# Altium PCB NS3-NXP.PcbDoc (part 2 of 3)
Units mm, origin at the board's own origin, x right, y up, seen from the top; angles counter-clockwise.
Board outline 147 x 83 mm, 2 copper layers (Top Layer, Bottom Layer); 303 components, 312 nets, 1163 pads, 118 vias.
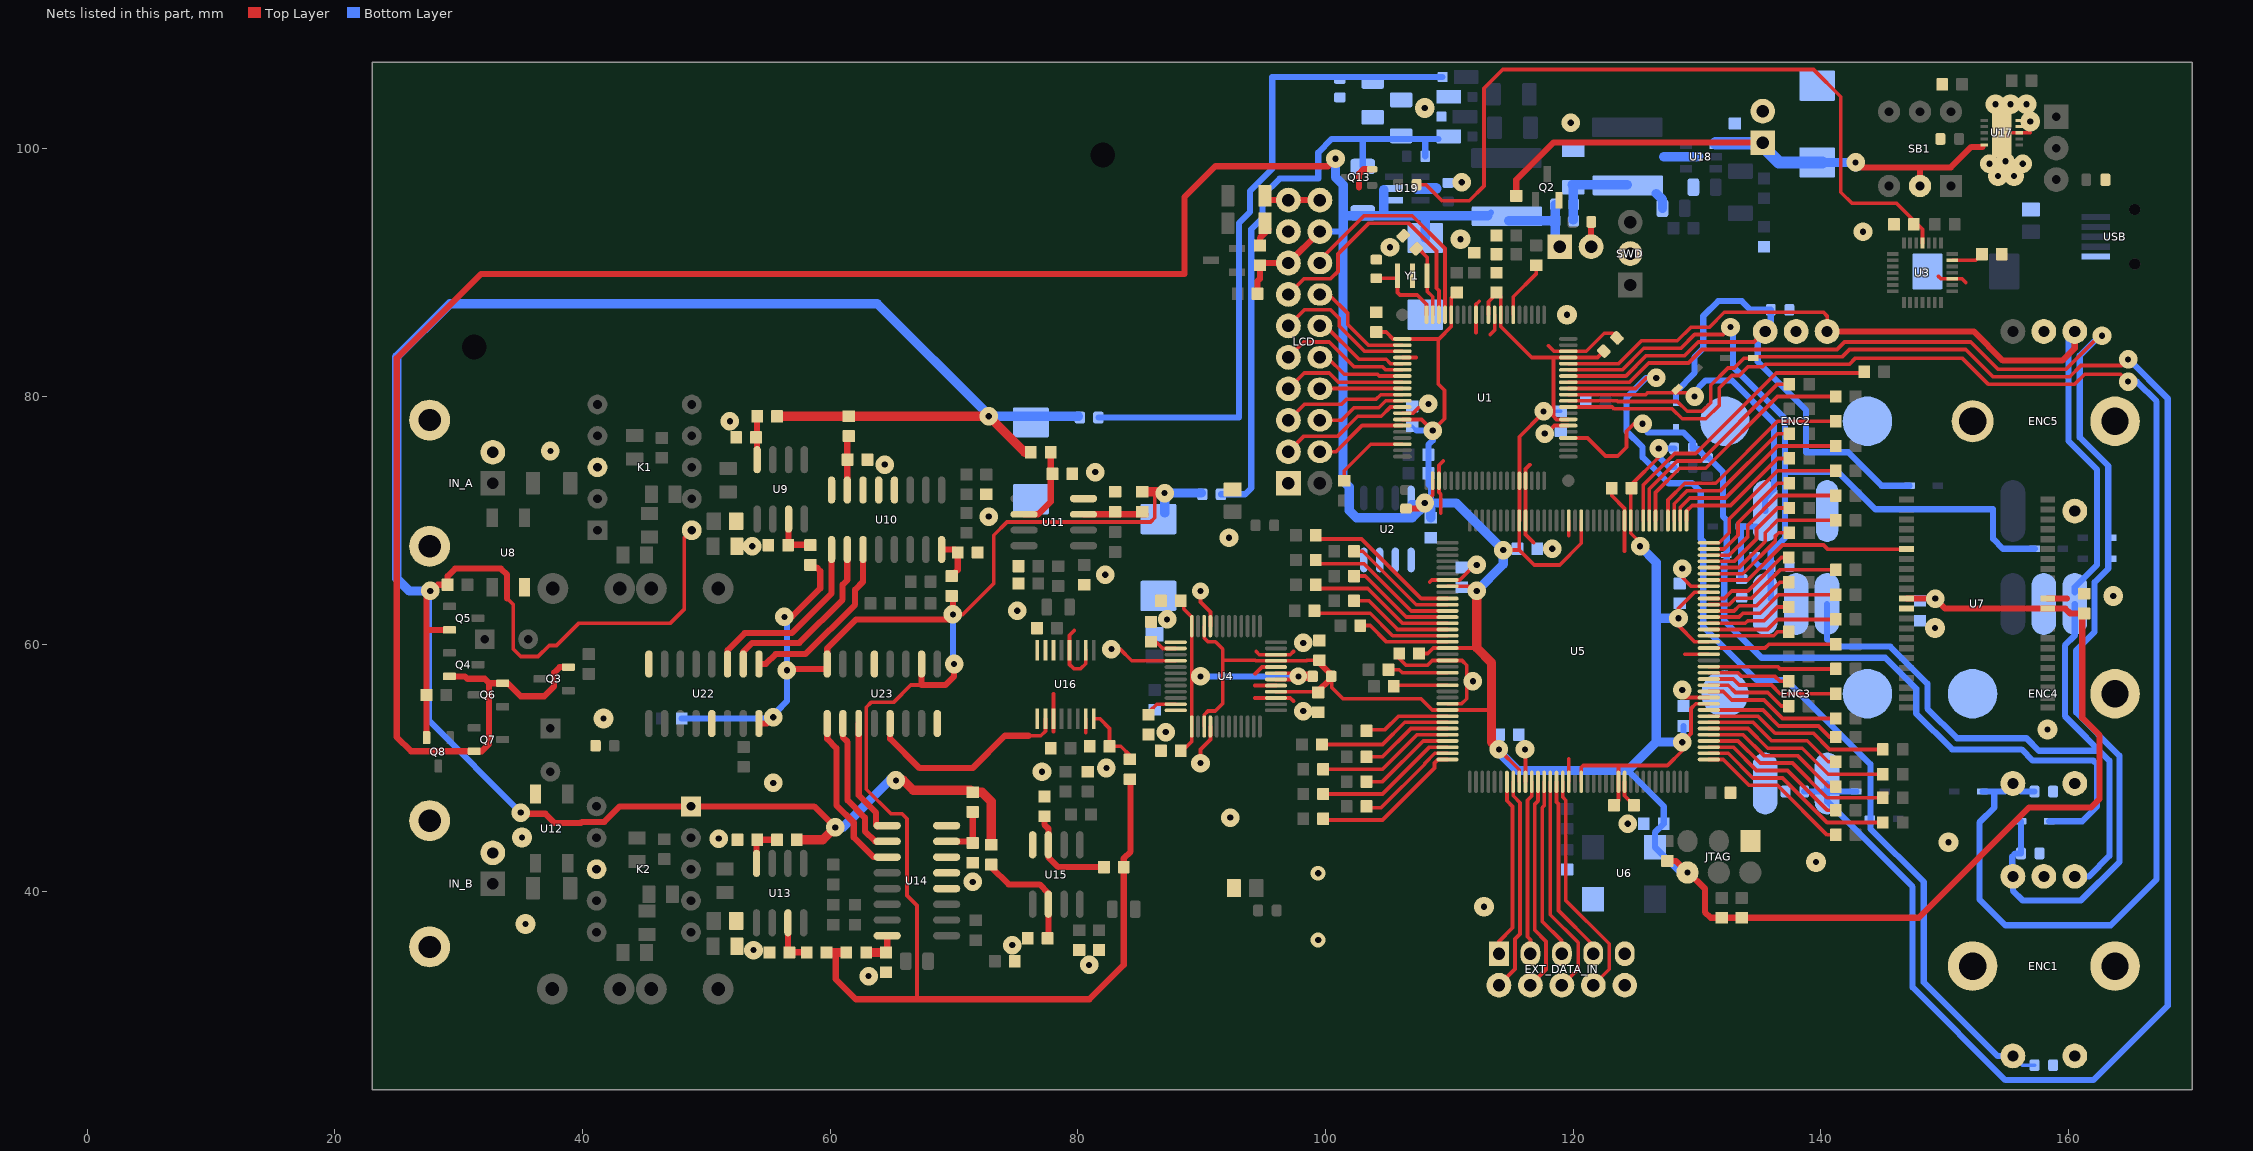
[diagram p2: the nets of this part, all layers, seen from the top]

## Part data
B1 B2 B3 B4 B5 B6 B7 B8 B9 B10 B11 B12 B13 B14: library part BLM18PG181SN1D, "Bead 0603 size for power lines"
B15 B16 B17 B18: library part BLM18AG601SN1D, "0603 size for general signal lines"
BATERY BOOZ: "Header, 2-Pin"
C1 C2 C3 C4 C5 C6 C9 C12 C13 C14 C16 C17 C18 C19 C20 C21 C23 C24 C25 C26 C28 C29 C30 C32 C33 C34 C45 C46 C47 C48 C51 C52 C60 C61 C62 C63 C66 C67 C70 C83 C84: library part CL10B104KB8NNNC
C7 C8: library part CL10C220JB8NNNC
C10 C49 C64: library part GRM188R61C225KE15D
C11 C81: library part 293D476X9010D2T
C15 C50 C65 C80: library part GRM21BR61A106KE19L
C40 C55: library part GRM31C5C1H104JA01L
C41 C43 C56 C58: "Variable or Adjustable Capacitor"
C42 C57: library part CL21C222JBFNNNE
C44 C53 C59 C68: library part C0603C151J5GAC7867
C54 C69: "Aluminium Electrolitic Capacitor"
C71: library part GRM188R61C225KE15D, "General Purpose"
C86 C88 C89 C90 C92: library part GRM31CR71H475KA12L
C87 C91 C93: library part TR3D107K016C0150
C110 C111 C112 C113 C114 C115 C116 C117: library part CL10C102JB8NNNC
D1: library part D_C_LightDiode_3pin_OA
D2 D22: library part LL4151-GS8, "Small Signal Fast Switching Diode"
D5 D6 D7 D8 D9 D10 D11 D12 D13 D14 D15 D16 D17: library part PMEG2020EJ,115, "20V, 2A very low VF MEGA Schottky barrier rectifiers"
D18 D19 D20 D21: library part MSS1P3L-M3/89A, "30V, 1A, eSMP, Surface Mount Schottky Barrier Rectifiers"
ENC1 ENC2 ENC3 ENC4 ENC5: "Rotary Encoder with button"
EXT_DATA_IN: library part BH-10_2
IN_A IN_B: "BNC Elbow Connector"
JTAG: "Header, 3-Pin, Dual row"
K1 K2: library part A–5W–K, "5V переключающее реле."
L1 L2: library part NR6028T220M, "Shielded Power Inductor Wire Wound H=2.8mm"
LCD: "Header, 10-Pin, Dual row"
Q1: "NPN General-purpose Transistor"
Q2 Q5 Q8: library part IRLML2402TRPBF, "20V, 0.25 Ohm, Single N-Channel HEXFET Power MOSFET"
Q3 Q4 Q6 Q7: library part IRLML6302TRPBF, "20V, 0.7A Single P-Channel HEXFET Power MOSFET"
Q13: library part MMBT3904WT1G, "40 V, 200 mA NPN general-purpose transistors"
R1 R2 R9 R10 R12 R18 R19 R107 R108 R128 R136 R137 R150 R151 Rt: library part 0603SAF1002T50
R3 R8: library part CRCW12062R00FKEA
R6 R105 R125: library part TC0350F1002T5E, "TC03 (0603) 1/16W 1% 10.0K 50PPM T/R-5000"
R7: library part TC0350F5101T5E, "TC03 (0603) 1/16W 1% 5.1K 50PPM T/R-5000"
R14 R129: library part ERJ3EKF1001V
R15 R97 R117: library part 0603SAF1000T50
R20 R21 R22 R23 R24 R25 R26 R27 R28 R29 R30 R31 R32 R33 R34 R35 R36 R37 R38 R39 R40 R41 R42 R43 R44 R45 R46 R47 R48 R49 R50 R51 R52 R53 R54 R55 R56 R57 R58 R59 R60 R61 R62 R63 R64 R65 R66 R67 R68 R69 R70 R71 R72 R73 R74 R75 R76 R77 R78 R79 R80 R99 R100 R119 R120: library part 0603SAF330JT50
R88 R109 R130 R135: library part ERA3AED102V
R89 R90 R91 R110 R111 R112 R127: library part 0805S8F5100T50
R92 R93 R113: library part 0805S8F1002T50
R94 R114: library part 0805S8F1001T50
R95 R115: library part TC0350F4990T5E, "TC03 (0603) 1/16W 1% 499E 50PPM T/R-5000"
R96 R101 R116 R121: library part 0603SAF3300T50
R98: library part RR0816P-4992-D-68C
R102 R103 R122 R123: library part 0603SAF2701T50
R104 R124: library part RC0805FR-0710KL, "General Purpose Chip Resistor"
R106 R126: library part TC0310C3001T5E, "TC03 (0603) 1/16W 0.25% 3.00K 10PPM T/R-5000"
R118: library part 0805S8F4700T50
R131: library part 0603SAF2001T50
R132: library part 0603SAF1503T50
R133 R138: library part 0603SAF1003T50
R141 R142: library part 0805S8F1502T50
R143 R144 R145: library part 0603SAF2201T50
SWD: "Header, 3-Pin"
U1: library part LPC1758FBD80,551, "32-bit ARM Cortex-M3 MCU, 512kB flash 32kB SRAM with Ethernet, USB 2.0 Host/Device/OTG, CAN"
U2: library part M24C64MN1, "64 Kbit Serial IІC Bus EEPROM"
U3: "USB-RS232 Converter"
U4: "2 x 8bit 100MSPS ADC converter"
U5: library part QFP-144, "PQFP-144/TQFP-144"
U6: library part KXO-V97, "Clock Oscillator"
U7: "SRAM"
U8 U12: "Opto Switch"
U10 U14: library part MC74HC4051AD, "Analog Multiplexer/Demultiplexer"
U17: "Li-Ion Battery Charger"
U18: "DC-DC Step-Down converter"
U19: library part MT3608, "2A Step Up Converter"
U22 U23: library part M74HC595M1R, "8 Bit Shift Register with Output Latches (3 STATE)"
USB: library part "USB MINIB"
Y1: library part CSTCE10M0G55Z-R0, "SMD 10 MHz 0.5%, 0.2%(TC) Build in Load Capacitance 33pF ± 20%"

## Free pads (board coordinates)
  round 1.524 hole 2: 0(31.25,84) 0(82,99.5)

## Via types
v1: diameter 1.5, hole 0.5, Top Layer to Bottom Layer, 93 vias
v2: diameter 1.6, hole 0.5, Top Layer to Bottom Layer, 18 vias
v3: diameter 1.4, hole 0.5, Top Layer to Bottom Layer, 4 vias
v4: diameter 1.2, hole 0.5, Top Layer to Bottom Layer, 2 vias
v5: diameter 1.3, hole 0.5, Top Layer to Bottom Layer, 1 vias

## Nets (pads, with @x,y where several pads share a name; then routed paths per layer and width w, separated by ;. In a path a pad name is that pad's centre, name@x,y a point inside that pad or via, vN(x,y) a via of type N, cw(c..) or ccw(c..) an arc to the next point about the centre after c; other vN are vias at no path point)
0A: U10.11 U22.1 | length 14.5
  Top Layer w0.5: U22.1@54.245,58.4 54.8,58.4 55.6,59.2 58,59.2 62,63.2 62,64.4 62.645,65.045 U10.11@62.645,67.65
0B: U14.11 U23.1 | length 13.4
  Top Layer w0.5: U23.1@59.755,53.6 59.755,52.345 60.5,51.6 60.5,47 61.9,45.6 61.9,44.4 63.495,42.805 U14.11@64.6,42.805
1A: U10.10 U22.2 | length 15
  Top Layer w0.5: U22.2@52.975,58.4 52.975,59.375 53.7,60.1 57.5,60.1 61,63.6 61,64.8 61.375,65.175 U10.10@61.375,67.65
1B: U14.10 U23.2 | length 11.6
  Top Layer w0.5: U23.2@61.025,53.6 61.025,52.475 61.4,52.1 61.4,47.4 62.8,46 62.8,44.9 63.625,44.075 U14.10@64.6,44.075
2A: U10.9 U22.3 | length 15
  Top Layer w0.5: U22.3@51.705,58.4 51.705,59.505 53.1,60.9 56.9,60.9 60.105,64.105 U10.9@60.105,67.65
2B: U14.9 U23.3 | length 8.9
  Top Layer w0.5: U23.3@62.295,53.6 62.295,47.805 63.7,46.4 63.7,45.4 U14.9@63.8,45.3
+2.7V: B1.2 B15.2 B16.2 BOOZ.1 C1.2 C3.2 C4.2 C5.2 C6.2 C9.1 C18.1 C19.1 C20.2 C21.2 C23.1 C24.1 C25.1 C26.1 C28.1 C29.1 C30.1 C32.1 C33.1 C34.1 C87.A D22.A JTAG.6 L2.1 LCD.15 LCD.18 Q3.2 Q4.2 Q6.2 Q7.2 R1.2 R6.2 R9.2 R10.2 R12.2 R76.1 R77.1 R79.1 R150.2 R151.2 U1.8 U1.10 U1.16 U1.21 U1.34 U1.42 U1.56 U1.67 U1.77 U2.8 U4.15 U4.28 U4.33 U4.46 U5.9 U5.19 U5.25 U5.46 U5.56 U5.64 U5.82 U5.90 U5.100 U5.116 U5.126 U5.136 U6.4 U7.11 U7.33 U19.4 U19.5 | length 523
  Top Layer w0.3: U4.15@90.198,53.354 90.198,54.298 90.499,54.598 91.098,54.598 91.7,55.2 91.7,59.6 91.1,60.2 90.5,60.2 90.198,60.502 U4.46@90.198,61.454 ; 91.7,58.7 94.308,58.7 94.354,58.654 U4.33@95.998,58.654 98.454,58.654 98.5,58.7 C18.1@99.25,58.7 ; U4.28@95.998,56.154 C19.1@99.246,56.154 ; B1.2@100.5,57.3 100.5,56.5 101.4,55.6 107.7,55.6 108.614,54.686 U5.136@109.846,54.686 113.4,54.686 ; C5.2@104.1,85.2 104.9,85.2 105.45,84.65 U1.21@106.2,84.65 109.15,84.65 110.15,85.65 U1.16@110.15,86.6 110.15,87.95 R12.2@110.6,88.4 ; U1.34@106.2,78.15 107.75,78.15 v1(108.65,77.25) 109.6,78.2 109.6,80.5 109.1,81 109.1,84.65 ; C21.2@107.55,59.25 108.25,59.25 108.686,59.686 U5.126@109.846,59.686 112.2,59.686 ; v1(108,71.4) 108.65,72.05 U1.42@108.65,73.2 ; U5.116@109.846,64.686 111.814,64.686 v1(112.2,64.3) ; U1.10@113.15,86.6 113.15,87.65 113.6,88.1 114.15,88.1 U1.8@114.15,86.6 114.15,85.65 116.65,83.15 118.4,83.15 ; v1(114,51.5) 115.646,49.854 U5.9@115.646,48.886 ; v1(114.35,67.6) 115.646,67.6 ; U5.100@115.646,69.986 115.646,67.6 ; U5.100@115.65,69.99 U1.56@115.65,73.2 115.65,76.75 117.6,78.7 v1(117.6,78.8) ; U1.67@119.6,78.15 118.65,78.15 118.4,78.4 118.4,83.15 ; U5.19@120.646,48.886 120.646,50.046 120.8,50.2 123.646,50.2 ; U5.90@120.646,69.986 120.646,68.146 118.9,66.4 116.846,66.4 115.646,67.6 ; C24.1@122.47,83.67 121.95,83.15 U1.77@119.6,83.15 118.4,83.15 ; C28.1@123.3,47 123.646,47.346 U5.25@123.646,48.886 123.646,50.2 ; C23.1@124.646,72.5 U5.82@124.646,69.986 124.646,68.954 v1@125.5,68.1 ; C23.1@124.7,72.5 124.7,72.9 126.9,75.1 v1(126.9,75.8) ; U5.46@130.946,55.186 129.886,55.186 129.5,54.8 129.5,52.782 v1(128.8,52.082) 128.8,51.4 127.6,50.2 123.646,50.2 ; U5.56@130.946,60.186 129.814,60.186 128.5,61.5 128.5,62.9 129.786,64.186 U5.64@130.946,64.186
  Top Layer w0.5: Q4.2@29.25,57.4 30.5,57.4 30.7,57.2 32.1,57.2 32.45,56.85 ; Q3.2@38.85,58.15 38.15,58.15 37.7,57.7 37.7,56.6 36.9,55.8 35,55.8 33.95,56.85 Q6.2@33.55,56.85 32.45,56.85 ; R6.2@94.5,88.3 94.5,89.3 94.7,89.5 C1.2@94.7,90.6 94.88,90.78 LCD.15@97,90.78 LCD.18@99.54,93.32 ; C19.1@99.3,56.1 B1.2@100.45,57.25 ; C18.1@99.3,58.7 B1.2@100.3,57.7 ; v1(100.8,99.2) 100.2,98.6 91.1,98.6 88.6,96.1 88.6,89.9 31.8,89.9 25,83.1 25,52.5 26.15,51.35 Q7.2@31.25,51.35 31.85,51.35 32.45,51.95 32.45,56.85 ; R1.2@106.5,70.95 107.55,70.95 v1(108,71.4) ; R76.1@127.5,42.5 128.28,42.5 JTAG.6@129.22,41.56 129.34,41.56 130.63,40.27 130.63,38.37 131.1,37.9 R77.1@132,37.9 R79.1@133.6,37.9 147.9,37.9 156.8,46.8 161.8,46.8 162.5,47.5 162.5,52.648 161.1,54.048 161.1,62.324 C33.1@161.252,62.476 160.124,62.476 159.724,62.876 U7.33@158.316,62.876 150.024,62.876 v1(149.224,63.676) ; U7.11@146.916,63.676 v1@149.2,63.676
  Top Layer w0.75: v1(112.2,64.3) 112.2,59.7 113.4,58.5 113.4,54.686 113.4,52.1 v1(114,51.5)
  Bottom Layer w0.3: C4.2@107,77.6 C4.2@107.35,77.25 ; v1(117.6,78.8) C3.2@119,78.8
  Bottom Layer w0.5: LCD.18@99.54,93.32 101.4,93.32 101.42,93.32 ; U2.8@106.905,71.4 v1(108,71.4) 108.5,71.9 108.5,72.7 108.3,72.9 R9.2@108.3,73.8 R10.2@108.3,75.3 108.3,76.1 108.65,76.45 v1(108.65,77.25) C4.2@107.35,77.25 ; L2.1@113.095,94.6 L2.1@113.345,94.85 ; 124.4,49.8 127.3,46.9 C34.1@127.3,45.5 126.6,44.8 U6.4@126.6,43.6 128.64,41.56 JTAG.6@129.22,41.56 ; R151.2@128.15,74.3 127.75,74.3 126.9,75.15 v1(126.9,75.8) R150.2@128.15,75.8 ; v1@128.9,52.1 C30.1@128.9,53.4 ; C32.1@147.8,63.676 v1(149.224,63.676)
  Bottom Layer w0.75: v1(100.8,99.2) 100.8,97.7 101.42,97.08 101.42,93.32 ; 101.4,93.32 101.4,73.2 101.9,72.7 101.9,70.8 102.5,70.2 107,70.2 108,71.2 v1(108,71.4) ; 101.42,94.6 104.7,94.6 ; 104.7,96.7 104.7,94.6 ; C87.A@108.05,92.8 108.05,94.55 ; C9.1@108.5,70.2 108.5,70.9 v1(108,71.4) ; v1(112.2,64.3) 114.35,66.45 v1(114.35,67.6) 110.55,71.4 v1(108,71.4) ; L2.1@113.095,94.6 104.7,94.6 ; v1(114,51.5) 114,51.3 115.5,49.8 124.4,49.8 126.7,52.1 ; L2.1@114.795,94.2 B15.2@118.55,94.2 ; B16.2@118.55,95.5 B15.2@118.55,94.2 ; BOOZ.1@118.8,92.1 BOOZ.1@118.9,92.1 118.55,92.45 B15.2@118.55,94.2 ; v1(125.4,67.9) 126.7,66.6 126.7,62.1 ; v1(128.5,62.1) 126.7,62.1 ; v1@128.9,52.1 126.7,52.1 ; 126.7,52.1 126.7,62.1
+3.3VA: B2.2 B4.2 B6.2 B8.2 B10.2 B12.2 B14.2 B17.2 C91.A R107.2 U22.16 U23.10 U23.16 | length 154.8
  Top Layer w0.3: 67,31.325 67,38.9 66.2,39.7 66.2,45.9 65.8,46.3 64.9,46.3 62.91,48.29 62.91,54.91 63.3,55.3 65.1,55.3 66.5,56.7 67.375,56.7 ; v1(69.9,62.4) 70.7,62.4 73.2,64.9 73.2,68.8 74.265,69.865 85.865,69.865 86.2,70.2 86.2,72.3
  Top Layer w0.5: U22.16@54.245,53.6 54.9,53.6 v1(55.4,54.1) ; v1(56.3,62.2) 56.9,62.2 59.2,64.5 59.2,65.9 58.9,66.2 58.6,66.2 B2.2@58.4,66.4 ; v1(56.5,57.9) 56.5,58 U23.16@59.7,58 ; U23.16@59.755,59.4 59.755,59.655 62.1,62 v1@69.5,62 ; 60.45,35.1 60.45,32.95 62.075,31.325 67,31.325 80.925,31.325 83.7,34.1 83.7,42.7 84.25,43.25 B14.2@84.25,49.1 ; U23.10@67.375,58.4 67.375,56.7 69.3,56.7 70,57.4 v1(70,58.4) ; v1@69.6,58.4 v1@69.9,58.4 ; v1(69.9,62.4) B4.2@69.9,63.8
  Top Layer w0.75: B8.2@59.7,35.1 60.45,35.1 B10.2@61.3,35.1 ; B6.2@85.2,72.3 v1@86.9,72.3
  Bottom Layer w0.5: R107.2@48,54 55.3,54 v1(55.4,54.1) 55.7,54.1 55.7,54.6 56.5,55.4 v1(56.5,57.9) 56.5,62 v1(56.3,62.2) ; v1@69.9,58.4 v1(69.9,62.4) v1@69.95,62.45
  Bottom Layer w0.75: C91.A@87,70.6 v1(87,72.2) B17.2@89.95,72.2
-3.3VA: B3.1 B5.1 B7.1 B9.1 B11.1 B13.1 B18.2 C93.C K1.10 K2.1 Q5.2 Q8.2 R108.1 R128.1 | length 223.2
  Top Layer w0.3: 33.9,63.7 34.4,63.2 34.4,59.6 35,59 36.4,59 37.3,59.9 37.9,59.9 39.7,61.7 47.1,61.7 48.2,62.8 48.2,68.58 K1.10@48.82,69.2
  Top Layer w0.5: Q8.2@27.4,52.45 R128.1@27.4,55.9 27.4,63.9 28.3,64.8 R108.1@29.1,64.8 29.1,65.5 29.7,66.1 33.4,66.1 33.9,65.6 33.9,63.7 ; 27.45,61.15 Q5.2@29.25,61.15 ; v1@35.1,46.3 37,46.3 37.75,45.55 39.85,45.55 39.95,45.65 41.75,45.65 43,46.9 K2.1@48.75,46.9 58.7,46.9 v1(60.4,45.2)
  Top Layer w0.75: B3.1@55.7,78.4 B5.1@61.4,78.4 ; B9.1@57.3,44.2 59.4,44.2 v1(60.4,45.2) ; B5.1@61.5,78.4 v1(72.8,78.4) 75.7,75.5 B7.1@76.2,75.5 ; v1(65.3,49) 65.9,49 66.7,48.2 71.35,48.2 B11.1@71.5,48.05 72.25,48.05 73,47.3 B13.1@73,43.8
  Bottom Layer w0.5: v1(27.7,64.3) 27.6,64.2 27.6,53.8 35,46.4 35,46.199 v1@34.901,46.1
  Bottom Layer w0.75: v1(27.7,64.3) 26,64.3 25,65.3 25,83.2 29.3,87.5 63.8,87.5 72.8,78.5 v1(72.8,78.4) B18.2@80.05,78.4 ; v1(60.4,45.2) 61,45.2 64.8,49 v1(65.3,49)
  other v1: 35,46.4
A0: R55.2 U5.71 | length 9.3
  Top Layer w0.3: U5.71@130.946,67.686 132.186,67.686 133.3,68.8 133.3,69.8 136.5,73 R55.2@137.45,73
A1: R56.2 U5.70 | length 12.8
  Top Layer w0.3: U5.70@130.946,67.186 132.586,67.186 134.1,68.7 134.1,69.6 136.5,72 R56.2@141.2,72
A2: R57.2 U5.69 | length 8.8
  Top Layer w0.3: U5.69@130.946,66.686 132.986,66.686 134.8,68.5 134.8,69.3 136.5,71 R57.2@137.45,71
A3: R58.2 U5.68 | length 12.2
  Top Layer w0.3: U5.68@130.946,66.186 133.386,66.186 135.5,68.3 135.5,69 136.5,70 R58.2@141.2,70
A4: R59.2 U5.67 | length 8.1
  Top Layer w0.3: U5.67@130.946,65.686 133.686,65.686 136.3,68.3 136.3,68.7 136.6,69 R59.2@137.45,69
A5: R60.2 U5.52 | length 10.3
  Top Layer w0.3: U5.52@130.946,58.186 136.514,58.186 136.7,58 R60.2@141.2,58
A6: R61.2 U5.51 | length 6.7
  Top Layer w0.3: U5.51@130.946,57.686 133.314,57.686 133.6,57.4 136.3,57.4 136.7,57 R61.2@137.4,57
A7: R62.2 U5.50 | length 10.7
  Top Layer w0.3: U5.50@130.946,57.186 132.914,57.186 133.4,56.7 136,56.7 136.7,56 R62.2@141.2,56
A8: R63.2 U5.49 | length 7.2
  Top Layer w0.3: U5.49@130.946,56.686 132.514,56.686 133.1,56.1 135.7,56.1 136.8,55 R63.2@137.4,55
A9: R64.2 U5.48 | length 11.2
  Top Layer w0.3: U5.48@130.946,56.186 132.114,56.186 132.8,55.5 135.4,55.5 136.9,54 R64.2@141.2,54
A10: R65.2 U5.37 | length 12.8
  Top Layer w0.3: U5.37@130.946,50.686 132.114,50.686 134.2,48.6 136.5,48.6 140.5,44.6 R65.2@141.2,44.6
A11: R66.2 U5.38 | length 16.4
  Top Layer w0.3: U5.38@130.946,51.186 132.514,51.186 134.5,49.2 136.9,49.2 140.5,45.6 R66.2@145,45.6
A12: R67.2 U5.39 | length 12.4
  Top Layer w0.3: U5.39@130.946,51.686 132.914,51.686 134.8,49.8 137.3,49.8 140.5,46.6 R67.2@141.2,46.6
A13: R68.2 U5.40 | length 16
  Top Layer w0.3: U5.40@130.946,52.186 133.314,52.186 135.1,50.4 137.7,50.4 140.5,47.6 R68.2@145,47.6
A14: R69.2 U5.41 | length 12
  Top Layer w0.3: U5.41@130.946,52.686 133.714,52.686 135.4,51 138.1,51 140.6,48.5 R69.2@141.2,48.5
A15: R70.2 U5.78 | length 20
  Top Layer w0.3: U5.78@126.646,69.986 126.646,72.246 128.6,74.2 130.7,74.2 136.5,80 R70.2@141.2,80
A16: R71.2 U5.79 | length 17.4
  Top Layer w0.3: U5.79@126.146,69.986 126.146,72.546 128.4,74.8 130.3,74.8 136.5,81 R71.2@137.45,81
A17: R72.2 U5.80 | length 24.5
  Top Layer w0.3: U5.80@125.646,69.986 125.646,72.846 128.2,75.4 129.9,75.4 136.4,81.9 143.4,81.9 R72.2@143.5,82
ACLK: R20.1 U5.130 | length 4.9
  Top Layer w0.3: R20.1@105.074,57.942 105.948,57.942 106.204,57.686 U5.130@109.846,57.686
AD0: R22.2 U5.125 | length 7.6
  Top Layer w0.3: R22.2@102.8,61.5 103.6,61.5 104.914,60.186 U5.125@109.846,60.186
AD1: R23.2 U5.124 | length 11.6
  Top Layer w0.3: R23.2@99.1,62.7 99.3,62.5 103.6,62.5 105.414,60.686 U5.124@109.846,60.686
AD2: R24.2 U5.123 | length 8.5
  Top Layer w0.3: R24.2@102.3,63.5 103.5,63.5 105.8,61.2 ; 105.8,61.186 U5.123@109.846,61.186
AD3: R25.2 U5.122 | length 11.9
  Top Layer w0.3: R25.2@99.2,64.8 99.5,64.5 103.4,64.5 106.214,61.686 U5.122@109.846,61.686
AD4: R26.2 U5.121 | length 8.9
  Top Layer w0.3: R26.2@102.3,65.5 103.2,65.5 106.514,62.186 U5.121@109.846,62.186
AD5: R27.2 U5.120 | length 12.4
  Top Layer w0.3: R27.2@99.2,66.8 99.5,66.5 103.1,66.5 106.914,62.686 U5.120@109.846,62.686
AD6: R28.2 U5.119 | length 9.3
  Top Layer w0.3: R28.2@102.3,67.5 103,67.5 107.314,63.186 U5.119@109.846,63.186
AD7: R29.2 U5.118 | length 12.8
  Top Layer w0.3: R29.2@99.2,68.8 99.5,68.5 102.9,68.5 107.714,63.686 U5.118@109.846,63.686
AD8: R30.2 U5.137 | length 7.1
  Top Layer w0.3: R30.2@103.3,53.3 103.5,53.1 104.8,53.1 105.886,54.186 U5.137@109.846,54.186
AD9: R31.2 U5.138 | length 10.9
  Top Layer w0.3: R31.2@99.7,51.9 104.6,51.9 106.386,53.686 U5.138@109.846,53.686
AD10: R32.2 U5.139 | length 7.5
  Top Layer w0.3: R32.2@103.3,50.9 104.6,50.9 106.886,53.186 U5.139@109.846,53.186
AD11: R33.2 U5.140 | length 11.2
  Top Layer w0.3: R33.2@99.8,49.9 104.6,49.9 107.386,52.686 U5.140@109.846,52.686
AD12: R34.2 U5.141 | length 7.9
  Top Layer w0.3: R34.2@103.3,48.9 104.6,48.9 107.886,52.186 U5.141@109.846,52.186
AD13: R35.2 U5.142 | length 11.6
  Top Layer w0.3: R35.2@99.8,47.9 104.6,47.9 108.386,51.686 U5.142@109.846,51.686
AD14: R36.2 U5.143 | length 8.4
  Top Layer w0.3: R36.2@103.3,46.8 104.5,46.8 108,50.3 108,50.372 108.814,51.186 U5.143@109.846,51.186
AD15: R37.2 U5.144 | length 12.3
  Top Layer w0.3: R37.2@99.8,45.8 104.6,45.8 108.8,50 108.8,50.4 109.086,50.686 U5.144@109.846,50.686
AGND: C12.2 C13.2 C14.2 C15.1 C16.2 C17.2 C42.1 C45.1 C46.1 C47.2 C48.2 C49.1 C50.1 C51.2 C52.2 C53.1 C57.1 C60.1 C61.1 C62.2 C63.2 C64.1 C65.1 C66.2 C67.2 C68.1 C70.1 C71.1 C91.C C93.A IN_A.2 IN_B.2 K1.3 K2.8 R92.1 R100.1 R101.1 R103.1 R120.1 R121.1 R123.1 R127.1 U4.1 U4.4 U4.12 U4.16 U4.45 U8.2 U10.4 U10.5 U10.6 U10.8 U11.8 U12.2 U14.4 U14.5 U14.6 U14.8 U15.8 U16.2 U16.4 U16.6 U16.7 U16.8 U16.9 U16.11 U16.15 U22.8 U22.13 U23.8 U23.13 | length 21.8
  Top Layer w0.3: 78.025,52.925 U16.11@78.025,53.975 78.025,55.975 ; 79.7,61.1 79.325,60.725 U16.4@79.325,59.525 79.325,58.357 79.657,58.025 80.225,58.025 80.625,58.425 U16.2@80.625,59.525 ; 80.625,52.875 U16.15@80.625,53.975 ; v1(82.7,59.6) 83.4,59.6 84.346,58.654 U4.4@87.898,58.654 ; v1(89.9,50.4) 89.9,51.5 90.698,52.298 U4.16@90.698,53.354 ; v3(89.9,64.3) 89.9,63.4 90.698,62.602 U4.45@90.698,61.454
  other v1: 63.1,33.2 80.9,34.1 53.8,35.3 74.7,35.7 71.5,40.8 51,44.3 92.3,46 55.4,48.8 77.1,49.7 82.3,50 87.1,52.9 87.2,62 75.1,62.7 82.2,65.6 53.7,67.9 92.2,68.6 72.8,70.3 81.4,73.9 64.4,74.5 37.4,75.6 51.9,78
  other v2: 35.4,37.4 35.1,44.4 41.7,54
BACKLIGHT: R7.2 U1.38 | length 6.5
  Top Layer w0.3: R7.2@101.5,73.1 101.5,74 103.65,76.15 U1.38@106.2,76.15
BATT: BATERY.1 C81.A C83.2 R132.2 SB1.2 U17.10 U18.4 | length 48.2
  Top Layer w0.5: R132.2@115.4,96.2 115.4,97.5 118.4,100.5 BATERY.1@135.3,100.5 ; v1@142.5,99.3 143.3,98.5 148,98.5 ; SB1.2@148,97 148,98.5 ; 153.05,100.15 152.15,100.15 150.5,98.5 148,98.5
  Bottom Layer w0.75: C81.A@140.1,98.9 v1(142.8,98.9) v1@142.8,98.529 ; SB1.2@148,97 SB1.2@148,97.4
  Bottom Layer w1: U18.4@131.5,100.45 C83.2@133.05,100.45 135.05,100.45 136.6,98.9 C81.A@140.1,98.9
BCLK: R21.1 U5.132 | length 4.3
  Top Layer w0.3: R21.1@105.57,56.686 U5.132@109.846,56.686
BUZZER: R14.1 U1.6 | length 4.7
  Top Layer w0.3: U1.6@115.15,86.6 115.15,88.05 117,89.9 R14.1@117,90.5
CE_S-: U5.66 U7.6 | length 17.3
  Top Layer w0.3: U5.66@130.946,65.186 134.086,65.186 136.9,68 140.2,68 140.524,67.676 U7.6@146.916,67.676
CLK_S: R75.2 U5.76 | length 17.8
  Top Layer w0.3: U5.76@127.646,69.986 127.646,71.646 129,73 131.5,73 136.5,78 R75.2@141.2,78
D0: R39.1 U5.63 | length 7.7
  Top Layer w0.3: U5.63@130.946,63.686 132.186,63.686 132.8,64.3 134.1,64.3 136.8,67 R39.1@137.3,67
D1: R40.1 U5.62 | length 11.4
  Top Layer w0.3: U5.62@130.946,63.186 130.956,63.196 132.596,63.196 133.1,63.7 134.4,63.7 136.7,66 R40.1@141.2,66
D2: R41.1 U5.61 | length 7.4
  Top Layer w0.3: U5.61@130.946,62.686 132.986,62.686 133.4,63.1 134.8,63.1 136.7,65 R41.1@137.4,65
D3: R42.1 U5.60 | length 11
  Top Layer w0.3: U5.60@130.946,62.186 133.386,62.186 133.7,62.5 135.1,62.5 136.6,64 R42.1@141.2,64
D4: R43.1 U5.59 | length 6.9
  Top Layer w0.3: U5.59@130.946,61.686 133.886,61.686 134.1,61.9 135.4,61.9 136.5,63 R43.1@137.3,63
D5: R44.1 U5.58 | length 10.6
  Top Layer w0.3: U5.58@130.946,61.186 135.686,61.186 136.5,62 R44.1@141.2,62
D6: R45.1 U5.57 | length 6.5
  Top Layer w0.3: U5.57@130.946,60.686 136.186,60.686 136.5,61 R45.1@137.3,61
D7: R46.1 U5.55 | length 10.4
  Top Layer w0.3: U5.55@130.946,59.686 135.486,59.686 135.8,60 R46.1@141.2,60
D8: R47.1 U5.42 | length 15.6
  Top Layer w0.3: U5.42@130.946,53.186 134.114,53.186 135.7,51.6 138.5,51.6 140.6,49.5 R47.1@145,49.5
D9: R48.1 U5.43 | length 11.6
  Top Layer w0.3: U5.43@130.946,53.686 134.514,53.686 136,52.2 138.9,52.2 140.6,50.5 R48.1@141.2,50.5
D10: R49.1 U5.44 | length 15.2
  Top Layer w0.3: U5.44@130.946,54.186 134.914,54.186 136.3,52.8 139.4,52.8 140.7,51.5 R49.1@145,51.5
D11: R50.1 U5.45 | length 11.2
  Top Layer w0.3: U5.45@130.946,54.686 135.314,54.686 136.6,53.4 139.8,53.4 140.7,52.5 R50.1@141.2,52.5
D12: R51.1 U5.72 | length 13.3
  Top Layer w0.3: U5.72@130.946,68.186 131.786,68.186 132.6,69 132.6,70.1 136.5,74 R51.1@141.2,74
D13: R52.1 U5.73 | length 10.8
  Top Layer w0.3: U5.73@129.146,69.986 129.146,70.746 129.6,71.2 132.7,71.2 136.5,75 R52.1@137.45,75
D14: R53.1 U5.74 | length 15.7
  Top Layer w0.3: U5.74@128.646,69.986 128.646,71.046 129.4,71.8 132.3,71.8 136.5,76 R53.1@141.2,76
D15: R54.1 U5.75 | length 13
  Top Layer w0.3: U5.75@128.146,69.986 128.146,71.346 129.2,72.4 131.9,72.4 136.5,77 R54.1@137.45,77
DGND: BATERY.2 C1.1 C2.2 C3.1 C4.1 C5.1 C6.1 C7.1 C8.1 C9.2 C10.1 C11.C C18.2 C19.2 C20.1 C21.1 C23.2 C24.2 C25.2 C26.2 C28.2 C29.2 C30.2 C32.2 C33.2 C34.2 C80.1 C81.C C83.1 C84.1 C86.1 C87.C C90.1 C92.2 C110.1 C111.1 C112.1 C113.2 C114.1 C115.2 C116.2 D19.A D20.C ENC1.0 ENC1.2 ENC1.5 ENC2.0 ENC2.2 ENC2.5 ENC3.0 ENC3.2 ENC3.4 ENC4.0 ENC4.2 ENC4.5 ENC5.0 ENC5.2 ENC5.5 EXT_DATA_IN.9 EXT_DATA_IN.10 JTAG.1 LCD.1 LCD.17 Q2.2 Q13.2 R8.1 R18.1 R78.1 R80.2 R129.1 R131.1 R133.1 R136.2 R138.2 R142.1 R144.1 R145.2 Rt.1 SWD.2 U1.9 U1.12 U1.24 U1.33 U1.43 U1.57 U1.66 U1.78 U2.1 U2.2 U2.3 U2.4 U3.3 U4.27 U4.29 U4.32 U4.34 U5.10 U5.17 U5.26 U5.47 U5.54 U5.65 U5.83 U5.92 U5.99 U5.115 U5.128 U5.135 U6.2 U7.12 U7.34 U17.3 U17.4 U17.5 U17.11 U18.2 U19.2 USB.5 Y1.2 | length 85.9
  Top Layer w0.25: 155.464,101.3 156.9,101.3
  Top Layer w0.3: 94.3,55.654 U4.27@95.998,55.654 97.146,55.654 97.4,55.4 ; 94.3,56.654 U4.29@95.998,56.654 ; 94.3,57.6 94.854,58.154 U4.32@95.998,58.154 ; 94.4,59.4 94.646,59.154 U4.34@95.998,59.154 97.154,59.154 97.4,59.4 ; C21.1@105.95,59.25 105.95,58.85 106.5,58.3 108.228,58.3 108.614,58.686 U5.128@109.846,58.686 111.014,58.686 111.4,58.3 111.4,55.6 110.986,55.186 U5.135@109.846,55.186 ; U1.33@106.2,78.65 107.05,78.65 107.5,79.1 ; U1.24@106.2,83.15 107.3,83.15 ; 108.4,65 108.586,65.186 U5.115@109.846,65.186 110.836,65.186 112.05,66.4 v1(112.2,66.4) ; 109.3,70.6 109.3,72.117 109.16,72.257 109.16,73.19 U1.43@109.15,73.2 109.15,74.45 109.5,74.8 ; 112.15,85.15 U1.12@112.15,86.6 112.15,87.45 112.4,87.7 ; 113.3,85 113.65,85.35 U1.9@113.65,86.6 ; U5.10@116.146,48.886 v1@116.146,50.846 ; U5.99@116.146,69.986 116.146,68.854 116.8,68.2 ; U5.99@116.15,69.99 U1.57@116.15,73.2 116.15,74.15 116.5,74.5 ; v1@117.82,76.98 118.49,77.65 U1.66@119.6,77.65 ; 118,84.1 118.45,83.65 U1.78@119.6,83.65 121.05,83.65 122.5,85.1 123.161,85.1 C24.2@123.53,84.73 ; U5.17@119.646,48.886 119.646,50.754 ; 119.646,68.746 U5.92@119.646,69.986 ; C23.2@123.1,72.5 123.1,72 124.146,70.954 U5.83@124.146,69.986 124.146,67.504 ; U5.26@124.146,48.886 124.146,47.754 C28.2@124.9,47 ; v1@128.8,66 128.8,65.4 129.514,64.686 U5.65@130.946,64.686 ; v1@129.014,55.686 U5.47@130.946,55.686 ; 129.014,59.186 U5.54@130.946,59.186 ; 149.5,89.7 149.7,89.5 U3.3@150.6,89.5 151.4,89.5 151.7,89.2
  Top Layer w0.5: C1.1@94.7,92.2 94.7,92.8 R8.1@95.4,93.5 ; LCD.17@96.82,93.5 LCD.17@97,93.32 ; 102.7,96.9 102.7,98 103.05,98.35 Q13.2@103.75,98.35 ; U7.34@158.316,63.676 159.876,63.676
  Bottom Layer w0.5: v1@128.3,56.3 v1(128.8,56.3)
  Bottom Layer w0.75: 127.3,99.35 U18.2@129.1,99.35 130.15,99.35
  Bottom Layer w0.9: U19.2@107.4,96.8 108.9,96.8
  other v1: 124.4,45.5 116.1,51.5 98.2,54.6 111.9,57 98.2,60.1 128.8,66.1 118.3,67.7 117.7,77 108.3,79.4 105.2,92.05 143.4,93.3 111,97.3 153.6,98.8 156.3,98.8 154.9,99 119.8,102.1
  other v2: 112.8,38.8 139.6,42.4 150.3,44 158.3,53.1 149.2,61.3 163.6,63.9 119.5,86.6 110.9,92.7 154.3,97.8 155.6,97.8 156.9,102.2 108,103.3 154.1,103.6 155.3,103.6 156.6,103.6
  other v4: 99.4,36.1 99.4,41.5
ENC_B: ENC1.3 ENC2.3 ENC3.3 ENC4.3 ENC5.3 U1.76 | length 125.1
  Top Layer w0.3: U1.76@119.6,82.65 123.65,82.65 125.5,84.5 128.4,84.5 129.5,85.6 131,85.6 132.2,86.8 140.2,86.8 140.5,86.5 ENC2.3@140.5,85.25
  Top Layer w0.5: ENC2.3@140.5,85.25 152.35,85.25 154.7,82.9 159.5,82.9 160.5,83.9 ENC5.3@160.5,85.25
  Bottom Layer w0.5: ENC3.3@140.5,63.25 140.5,60.4 141.1,59.8 145.6,59.8 148.6,56.8 148.6,54.8 151,52.4 156.6,52.4 157.6,51.4 162.5,51.4 ; ENC1.3@160.5,41.25 161.65,41.25 163.3,42.9 163.3,50.6 159.7,54.2 159.7,59.9 160.5,60.7 ENC4.3@160.5,63.25 ; ENC4.3@160.5,64.2 160.5,64.6 162.3,66.4 162.3,74.1 160,76.4 160,84.75 ENC5.3@160.5,85.25
ENC_IRQ: C117.2 D6.A D8.A D10.A R150.1 U1.64 | length 73.1
  Top Layer w0.3: U1.64@119.6,76.65 121.15,76.65 122.6,75.2 123.6,75.2 124.3,75.9 124.3,77.2 124.9,77.8 v1(125.6,77.8)
  Bottom Layer w0.5: v1(125.6,77.8) 125.6,77.5 126,77.1 128.9,77.1 129.65,76.35 R150.1@129.65,75.8 130,75.8 130.7,75.1 130.9,75.1 132.1,73.9 132.1,70.3 132.4,70 132.4,66.8 132.2,66.6 132.2,61.9 135.2,58.9 145.2,58.9 147.7,56.4 147.7,54.4 150.6,51.5 156.2,51.5 157.1,50.6 162,50.6 162.3,50.3 162.3,46.9 161.1,45.7 D6.A@158.44,45.7
ENCA0: C110.2 D6.C D12.A D14.A ENC1.1 U1.73 | length 109.7
  Top Layer w0.3: U1.73@119.6,81.15 124.55,81.15 126.1,82.7 129.3,82.7 130.4,83.8 141.3,83.8 141.9,84.4 152.1,84.4 154.3,82.2 159.8,82.2 162.5,84.9 v1(162.7,84.9)
  Bottom Layer w0.5: ENC1.1@155.45,41.2 155.45,42.85 155.7,43.1 C110.2@156.15,43.1 D6.C@156.15,45.69 ; ENC1.1@155.5,41.25 155.5,40.1 156.3,39.3 161,39.3 164.1,42.4 164.1,51 160.6,54.5 160.6,59.5 162.1,61 162.1,65 163.2,66.1 163.2,74.4 160.9,76.7 160.9,83.3 162.5,84.9 v1(162.7,84.9)
ENCA1: C112.2 D8.C D13.A ENC2.1 U1.74 | length 54.6
  Top Layer w0.3: U1.74@119.6,81.65 124.25,81.65 125.9,83.3 129,83.3 130.1,84.4 134.6,84.4 135.2,85 135.2,85.3 135.25,85.25 ENC2.1@135.5,85.25
  Bottom Layer w0.5: D8.C@128.3,79.64 128.3,80.4 129.8,81.9 129.8,83.2 130.5,83.9 130.5,86.5 131.7,87.7 133.6,87.7 134.3,87 C112.2@135.95,87 135.95,85.7 ENC2.1@135.5,85.25 134.9,84.65 134.9,82.8 138.8,78.9 138.8,75.5 142.2,75.5 144.9,72.8 D13.A@147.16,72.8
ENCA2: C114.2 D10.C D15.A ENC3.1 U1.75 | length 64.6
  Top Layer w0.3: U1.75@119.6,82.15 123.95,82.15 125.7,83.9 128.7,83.9 129.8,85 132.1,85 v1(132.7,85.6)
  Bottom Layer w0.5: v1@133.1,85.3 132.9,85.1 132.9,82.4 137.1,78.2 137.1,73.9 ; D10.C@134.64,67.2 134.64,66.66 135,66.3 C114.2@135.95,66.3 ; ENC3.1@135.95,63.7 C114.2@135.95,66.3 ; D15.A@157.26,67.7 154.7,67.7 153.9,68.5 153.9,70.9 144.4,70.9 141.4,73.9 137.1,73.9 ; C114.2@135.95,66.3 135.95,67.45 137.1,68.6 137.1,73.9
ENCBUT0: C111.2 D5.C ENC1.4 U1.72 | length 81.9
  Top Layer w0.3: U1.72@119.6,80.65 125.05,80.65 125.9,81.5 v1(126.7,81.5)
  Bottom Layer w0.3: ENC1.4@155.5,26.75 156.25,26 C111.2@157.25,26
  Bottom Layer w0.5: v1(126.7,81.5) 125.9,81.5 124.3,79.9 124.3,77.2 125.6,75.9 125.6,75.1 127.7,73 129.6,73 130.3,72.3 130.3,68.5 130.5,68.3 130.5,61.4 134.8,57.1 137.2,57.1 144,50.3 144,45.1 148.3,40.8 148.3,32.7 154.25,26.75 ENC1.4@155.5,26.75
ENCBUT1: C113.1 D7.C D16.A ENC2.4 U1.71 | length 32
  Top Layer w0.3: U1.71@119.6,80.15 125.853,80.15 126.003,80.3 129.5,80.3 v1(129.8,80)
  Bottom Layer w0.5: v1(129.8,80) 129.6,80.2 130.7,81.3 132.8,81.3 136.2,77.9 136.2,72.5 135.5,71.8 ENC2.4@135.5,70.75 ; C113.1@133.54,65.31 D7.C@133.54,69.5 ENC2.4@134.8,69.5
ENCBUT2: C115.1 D9.C D17.A ENC3.5 U1.70 | length 153.2
  Top Layer w0.3: U1.70@119.6,79.65 123.55,79.65 123.6,79.6 128.4,79.6 129.2,78.8 130.4,78.8 131.1,79.5 131.1,80.9 132.5,82.3 133,82.3 133.8,83.1 D17.A@134.54,83.1 134.64,83.2 141.7,83.2 142.3,83.8 151.7,83.8 153.9,81.6 160.1,81.6 161,82.5 164.3,82.5 v1(164.8,83)
  Bottom Layer w0.5: C115.1@138.65,48.1 ENC3.5@140.5,48.1 ; ENC3.5@140.5,48.75 ENC3.5@140.5,48.1 ; D9.C@142.86,48.1 ENC3.5@140.5,48.1 ; v1(164.8,83) 164.838,83 168,79.838 168,30.8 162,24.8 154.9,24.8 147.4,32.3 147.4,40.4 140.5,47.3 ENC3.5@140.5,48.1
ENCBUT3: C116.1 D11.C ENC4.4 U1.69 | length 122.1
  Top Layer w0.3: U1.69@119.6,79.15 123.15,79.15 123.3,79 128,79 128.8,78.2 130.7,78.2 131.8,79.3 131.8,80.7 132.8,81.7 133.4,81.7 134.1,82.4 135.3,82.4 135.5,82.6 142.3,82.6 142.8,83.1 151.4,83.1 153.5,81 160.5,81 161.3,81.8 164.2,81.8 v1@164.7,81.3
  Bottom Layer w0.5: D11.C@153.04,48.1 154,48.1 ; C116.1@157.25,48.1 156.15,48.1 ENC4.4@155.5,48.75 154.85,48.1 154,48.1 ; v1@164.7,81.2 v1(164.8,81.2) 165.5,81.2 167.1,79.6 167.1,41 163.4,37.3 154.9,37.3 152.8,39.4 152.8,45.6 154,46.8 154,48.1
HOST_ACTIVE: R2.2 R18.2 U3.11 | length 61.4
  Top Layer w0.3: R2.2@107.35,97.1 108.1,97.1 109.4,95.8 111.6,95.8 112.8,97 112.8,104.9 114.3,106.4 139.4,106.4 141.6,104.2 141.6,99.397 141.6,96.5 142.5,95.6 146.1,95.6 148.2,93.5 U3.11@148.2,92.4
INTERL: U16.10 U23.5 | length 17
  Top Layer w0.3: 76,52.6 77,52.6 77.375,52.975 U16.10@77.375,53.975
  Top Layer w0.5: U23.5@64.835,53.6 64.835,52.365 67.2,50 71.5,50 74.1,52.6 76,52.6
IO0: EXT_DATA_IN.1 U5.7 | length 13.9
  Top Layer w0.3: EXT_DATA_IN.1@114,35.65 114,36 115.1,37.1 115.1,46.9 114.646,47.354 U5.7@114.646,48.886
IO1: EXT_DATA_IN.2 U5.8 | length 17.4
  Top Layer w0.3: EXT_DATA_IN.2@114,32.46 115.3,33.76 115.3,36.2 115.7,36.6 115.7,47.2 115.146,47.754 U5.8@115.146,48.886
IO2: EXT_DATA_IN.3 U5.11 | length 14.1
  Top Layer w0.3: EXT_DATA_IN.3@116.54,35 116.54,36.13 116.3,36.37 116.3,47.4 116.646,47.746 U5.11@116.646,48.886
IO3: EXT_DATA_IN.4 U5.12 | length 17.4
  Top Layer w0.3: EXT_DATA_IN.4@116.54,32.46 117.8,33.72 117.8,36 116.9,36.9 116.9,47.1 117.146,47.346 U5.12@117.146,48.886
IO4: EXT_DATA_IN.5 U5.13 | length 14
  Top Layer w0.3: U5.13@117.646,48.886 117.646,46.946 117.5,46.8 117.5,37.6 119.08,36.02 EXT_DATA_IN.5@119.08,35.65
IO5: EXT_DATA_IN.6 U5.14 | length 17.9
  Top Layer w0.3: U5.14@118.146,48.886 118.146,38.154 120.4,35.9 120.4,33.78 EXT_DATA_IN.6@119.08,32.46
IO6: EXT_DATA_IN.7 U5.15 | length 14.5
  Top Layer w0.3: U5.15@118.646,48.886 118.646,47.254 118.8,47.1 118.8,38.496 EXT_DATA_IN.7@121.646,35.65
IO7: EXT_DATA_IN.8 U5.16 | length 18.5
  Top Layer w0.3: U5.16@119.146,48.886 119.146,47.654 119.4,47.4 119.4,39.3 122.9,35.8 122.9,33.74 EXT_DATA_IN.8@121.62,32.46
LCS-: LCD.16 U1.17 | length 18.3
  Top Layer w0.3: LCD.16@99.54,90.78 99.54,91.04 103.1,94.6 107,94.6 109.65,91.95 U1.17@109.65,86.6
LD0: LCD.12 U1.25 | length 7.9
  Top Layer w0.3: LCD.12@99.54,85.7 100,85.7 102.7,83 104.9,83 105.25,82.65 U1.25@106.2,82.65
LD1: LCD.9 U1.26 | length 10.6
  Top Layer w0.3: LCD.9@97,83.16 98.24,84.4 100.3,84.4 102.3,82.4 104.6,82.4 104.85,82.15 U1.26@106.2,82.15
LD2: LCD.10 U1.27 | length 7.3
  Top Layer w0.3: LCD.10@99.54,83.16 100.14,83.16 101.5,81.8 104.2,81.8 104.35,81.65 U1.27@106.2,81.65
LD3: LCD.7 U1.28 | length 10
  Top Layer w0.3: LCD.7@97,80.62 98.28,81.9 100.3,81.9 101.05,81.15 U1.28@106.2,81.15
LD4: LCD.8 U1.29 | length 6.7
  Top Layer w0.3: LCD.8@99.54,80.65 U1.29@106.2,80.65
LD5: LCD.5 U1.30 | length 10.1
  Top Layer w0.3: LCD.5@97,78.08 98.3,79.38 101.28,79.38 101.68,79.78 104.08,79.78 104.45,80.15 U1.30@106.2,80.15
LD6: LCD.6 U1.31 | length 7.3
  Top Layer w0.3: LCD.6@99.54,78.08 101.28,78.08 102.3,79.1 104.3,79.1 104.85,79.65 U1.31@106.2,79.65
LD7: LCD.3 U1.32 | length 10.7
  Top Layer w0.3: LCD.3@97,75.54 98.26,76.8 101,76.8 102.6,78.4 104.5,78.4 105.25,79.15 U1.32@106.2,79.15
LLEDK: LCD.19 LCD.20 R3.1 | length 4.3
  Top Layer w0.5: R3.1@95.2,95.86 LCD.19@97,95.86 LCD.20@99.54,95.86
LRD-: LCD.11 U1.23 | length 11.5
  Top Layer w0.3: LCD.11@97,85.7 98.3,87 100.4,87 101.1,86.3 101.1,85.7 103.15,83.65 U1.23@106.2,83.65
LRES: LCD.4 U1.35 | length 7.5
  Top Layer w0.3: LCD.4@99.54,75.54 100.84,75.54 102.95,77.65 U1.35@106.2,77.65
LRS-: LCD.13 U1.18 | length 21.3
  Top Layer w0.3: LCD.13@97,88.24 98.26,89.5 100.4,89.5 101,90.1 101,91.5 103.5,94 106.7,94 108.95,91.75 108.95,88.75 109.15,88.55 U1.18@109.15,86.6
LWR-: LCD.14 U1.22 | length 8.9
  Top Layer w0.3: LCD.14@99.54,88.24 100.26,88.24 101.8,86.7 101.8,85.8 103.45,84.15 U1.22@106.2,84.15
NetB1_1: B1.1 C16.1 C17.1 U4.13 U4.30 U4.31 U4.48 | length 26.3
  Top Layer w0.3: C17.1@88.55,51.5 89.198,52.148 U4.13@89.198,53.354 v1@89.198,57.4 ; C16.1@88.55,63.5 88.55,62.85 89.198,62.202 U4.48@89.198,61.454 v1@89.198,57.4 ; v1@90.1,57.4 v1@89.198,57.4 ; U4.30@95.998,57.154 97.554,57.154 v3(97.8,57.4) 97.546,57.654 U4.31@95.998,57.654
  Top Layer w0.75: v3(97.8,57.4) B1.1@98.95,57.4
  Bottom Layer w0.5: v1(89.9,57.4) v3(97.8,57.4)
NetB2_1: B2.1 C45.2 U9.7 | length 3.8
  Top Layer w0.5: U9.7@56.635,70.1 56.635,68.035 B2.1@58.365,68.035
NetB3_2: B3.2 C46.2 U9.4 | length 3.5
  Top Layer w0.5: U9.4@54.095,74.9 B3.2@54.095,78.4
NetB4_1: B4.1 C47.1 U10.16 | length 3.5
  Top Layer w0.5: U10.16@68.995,67.65 70.05,67.65 C47.1@70.3,67.4 70.3,66 B4.1@69.8,65.5
NetB5_2: B5.2 C48.1 U10.7 | length 4.1
  Top Layer w0.5: U10.7@61.375,72.45 B5.2@61.375,76.575
NetB6_1: B6.1 C51.1 U11.7 | length 5
  Top Layer w0.5: U11.7@80.45,70.485 B6.1@85.435,70.485
NetB7_2: B7.2 C52.1 U11.2 | length 6.6
  Top Layer w0.5: U11.2@75.65,70.485 76.785,70.485 77.8,71.5 B7.2@77.8,75.5
NetB8_1: B8.1 C60.2 U13.7 | length 3.9
  Top Layer w0.5: U13.7@56.585,37.5 56.585,35.115 B8.1@58.085,35.115
NetB9_2: B9.2 C61.2 U13.4 | length 3.5
  Top Layer w0.5: U13.4@54.045,42.3 C61.2@54.045,44.2 ; C61.2@54.1,44.2 B9.2@55.7,44.2
NetB10_1: B10.1 C62.1 U14.16 | length 2.9
  Top Layer w0.5: C62.1@64.6,35.2 U14.16@64.6,36.455
  Top Layer w0.75: B10.1@62.9,35.1 C62.1@64.5,35.1
NetB11_2: B11.2 C63.1 U14.7 | length 4.5
  Top Layer w0.5: U14.7@69.4,44.075 C63.1@71.375,44.075 ; C63.1@71.5,43.95 B11.2@71.5,46.45
NetB12_1: B12.1 C66.1 U15.7 | length 8.3
  Top Layer w0.5: C66.1@77.3,46.1 77.3,45.43 77.615,45.115 U15.7@77.615,43.8 77.615,42.785 78.4,42 B12.1@82.1,42
NetB13_2: B13.2 C67.1 U15.2 | length 9.4
  Top Layer w0.5: B13.2@73,42.2 73,42 74.4,40.6 76.9,40.6 77.615,39.885 U15.2@77.615,39 C67.1@77.615,36.2
NetB14_1: B14.1 C70.2 U16.16 | length 5.3
  Top Layer w0.3: U16.16@81.275,53.975 81.775,53.975 82.55,53.2 C70.2@82.55,51.75 83.45,51.75 84.2,51 B14.1@84.2,50.7
NetB15_1: B15.1 B16.1 C86.2 L1.2 R141.2 | length 8.5
  Bottom Layer w0.75: C86.2@119.9,97.1 L1.2@124.35,97.1 ; B15.1@120,94.25 C86.2@120,96.9 ; L1.2@126.7,96.4 127.2,95.9 R141.2@127.2,95.2
NetB17_1: B17.1 C90.2 D18.C D22.C R143.2 | length 47.4
  Bottom Layer w0.5: B17.1@91.55,72.1 93.5,72.1 94,72.6 94,93.5 94.9,94.4 94.9,96.2 96.3,97.6 99.4,97.6 99.4,99.7 100.5,100.8 103,100.8 ; D22.C@103,98.575 103,100.8 ; R143.2@108.05,99.4 108.05,100.65 ; D18.C@109.1,100.8 109.05,100.8 103,100.8
NetB18_1: B18.1 C92.1 D21.A R145.1 | length 53.7
  Bottom Layer w0.5: B18.1@81.65,78.3 93,78.3 93,94 93.9,94.9 93.9,96.6 95.7,98.4 95.7,105.8 D21.A@109.45,105.8
NetBOOZ_2: BOOZ.2 R15.2 | length 2
  Top Layer w0.5: BOOZ.2@121.44,92.1 R15.2@121.44,94.09
NetC7_2: C7.2 U1.19 Y1.1 | length 5.8
  Top Layer w0.3: C7.2@107.5,91.95 108.2,91.25 Y1.1@108.2,89.75 108.2,88.5 108.65,88.05 U1.19@108.65,86.6
NetC8_2: C8.2 U1.20 Y1.3 | length 6.5
  Top Layer w0.3: C8.2@104.05,89.55 105.8,89.55 105.8,88.4 106,88.2 107.4,88.2 108.15,87.45 U1.20@108.15,86.6
NetC10_2: C10.2 U3.6 | length 2.6
  Top Layer w0.3: U3.6@150.6,91 152.5,91 C10.2@153,91.5
NetC12_1: C12.1 U4.11 | length 2.3
  Top Layer w0.3: C12.1@85.852,54.648 86.358,55.154 U4.11@87.898,55.154
NetC13_1: C13.1 U4.2 | length 2.3
  Top Layer w0.3: C13.1@85.852,60.16 86.34,60.16 86.846,59.654 U4.2@87.898,59.654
